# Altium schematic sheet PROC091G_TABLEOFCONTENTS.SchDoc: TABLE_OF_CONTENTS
size 431 x 279 mm; Date: Not shown in title block; ApprovedBy: Not shown in title block; CheckedBy: Not shown in title block; Author: Not shown in title block; CompanyName: Not shown in title block; DrawnBy: Antony/Bala; Engineer: Not shown in title block; Organization: Not shown in title block; Address1: Not shown in title block; Address2: Not shown in title block; Address3: Not shown in title block; Address4: Not shown in title block; DocumentNumber: 2; Revision: Use project parameter SCH_Rev; SheetNumber: 2; SheetTotal: 12; PageSetup: Record=PageOptions¦CenterHorizontal=True¦CenterVertical=True¦PrintScale=1.00¦XCorrection=1.00¦YCorrection=1.00¦PrintKind=0¦BorderSize=5000000¦LeftOffset=0¦BottomOffset=0¦Orientation=2¦PaperLength=1000¦PaperWidth=1000¦Scale=100¦PaperSource=15¦PrintQuality=600¦MediaType=1¦DitherType=10¦PaperKind=Letter¦PrintScaleMode=1
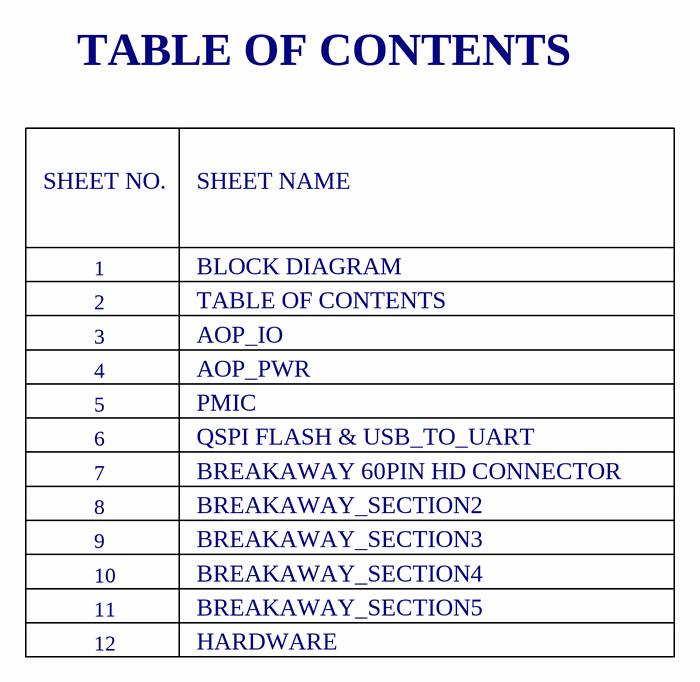
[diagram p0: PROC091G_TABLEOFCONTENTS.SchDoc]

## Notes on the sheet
- TABLE OF CONTENTS
- SHEET NO.
- SHEET NAME
- 1
- 2
- 3
- BLOCK DIAGRAM
- AOP_IO
- 4
- 5
- AOP_PWR
- PMIC
- 7
- 8
- 6
- QSPI FLASH & USB_TO_UART
- BREAKAWAY 60PIN HD CONNECTOR
- BREAKAWAY_SECTION2
- 9
- 10
- BREAKAWAY_SECTION3
- BREAKAWAY_SECTION4
- 11
- 12
- HARDWARE
- BREAKAWAY_SECTION5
